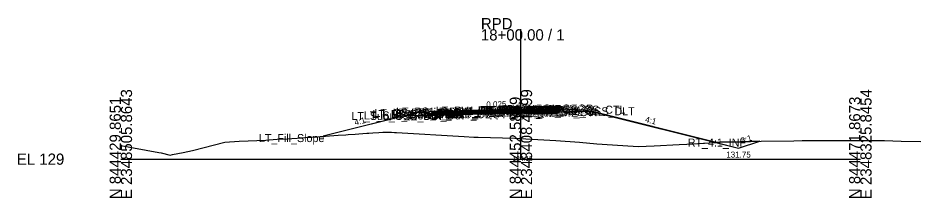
# Model space of a CAD drawing. Extents: x -26 to 2348536, y -510 to 844755.
# Drawn here: x -25.7 to 200, y 2990.3 to 3035.3 of the extents above; entities that cross this region are included whole.
import ezdxf

# ---------------------------------------------------------------- set-up
doc = ezdxf.new("R2010")
doc.units = 0
for name, color, linetype in [('Default', 7, 'Continuous'), ('Exist Cross Section Cell', 7, 'Continuous'), ('Exist XS Center Line Elevation Label', 7, 'Continuous'), ('Exist XS Ground Line', 7, 'Continuous'), ('Prop CMT Pvmt Course 1', 7, 'Continuous'), ('Prop CMT Pvmt Course 2', 7, 'Continuous'), ('Prop CMT Pvmt Course 3', 7, 'Continuous'), ('Prop CMT Pvmt Surface', 7, 'Continuous'), ('Prop CMT Pvmt Surface Shoulder', 7, 'Continuous'), ('Prop CMT Shld Paved Course 1', 7, 'Continuous'), ('Prop CMT Shld Paved Course 2', 7, 'Continuous'), ('Prop CMT Shld Paved Course 3', 7, 'Continuous'), ('Prop CMT Slope Grass', 7, 'Continuous'), ('Prop CMT Subgrade Earthwork', 7, 'Continuous'), ('Prop XS Ditch Standard Text', 7, 'Continuous'), ('Prop XS Earthwork Shape', 7, 'Continuous'), ('Prop XS SE Text', 7, 'Continuous'), ('Prop XS Side Slope Text', 7, 'Continuous'), ('Scratch_Level_0', 7, 'Continuous')]:
    doc.layers.add(name, color=color, linetype=linetype)

msp = doc.modelspace()

# ---------------------------------------------------------------- linework, layer by layer
at = {"layer": 'Exist Cross Section Cell'}
for p, q in [((100, 3000), (100, 3032.45)), ((0, 3000), (100, 3000)), ((100, 3000), (184.85, 3000))]:
    msp.add_line(p, q, dxfattribs=at)
at = {"layer": 'Exist XS Ground Line'}
msp.add_lwpolyline([(0, 3003.38), (9.47, 3001.7), (10.07, 3001.56), (12.37, 3001.02), (12.9, 3001.12), (15.58, 3001.62), (17.88, 3002.12), (25.98, 3004.25), (29.55, 3004.48), (36.25, 3004.75), (37.1, 3004.84), (39.08, 3004.97), (41.57, 3005.09), (42.72, 3005.17), (44.1, 3005.27), (46.87, 3005.46), (47.64, 3005.51), (49.26, 3005.61), (52.19, 3005.83), (54.3, 3005.96), (56.2, 3006.11), (56.84, 3006.15), (58.61, 3006.28), (59.47, 3006.34), (61.45, 3006.47), (62.02, 3006.51), (62.97, 3006.57), (64.5, 3006.68), (65.52, 3006.7), (67.27, 3006.73), (67.68, 3006.71), (68.44, 3006.68), (68.94, 3006.66), (85.83, 3005.64), (88.2, 3005.5), (89.31, 3005.47), (98.47, 3005.23), (100, 3005.15), (101.26, 3005.08), (108.74, 3004.68), (114.65, 3004.21), (119.01, 3003.85), (128.05, 3003.27), (129.28, 3003.2), (133.32, 3003.36), (139.55, 3003.63), (141.44, 3003.75), (149.82, 3004.21), (154.84, 3004.36), (160.09, 3004.53), (168.23, 3004.61), (170.35, 3004.65), (177.33, 3004.65), (180.62, 3004.65), (181.62, 3004.66), (190.89, 3004.68), (195.02, 3004.53), (200, 3004.44)], dxfattribs=at)
at = {"layer": 'Prop CMT Pvmt Course 1'}
for p, q in [((100, 3012.44), (88, 3012.14)), ((88, 3011.89), (100, 3012.19)), ((88, 3012.14), (88, 3011.89)), ((100, 3012.44), (104, 3012.54)), ((100, 3012.19), (100, 3012.44)), ((100, 3012.19), (100, 3012.44)), ((100, 3012.19), (100, 3012.31)), ((100, 3012.31), (100, 3012.31)), ((100, 3012.31), (100, 3012.19)), ((100, 3012.19), (100, 3012.31)), ((100, 3012.31), (100, 3012.31)), ((100, 3012.31), (100, 3012.19)), ((104, 3012.29), (100, 3012.19)), ((100, 3012.19), (100, 3012.19)), ((100, 3012.19), (100, 3012.19)), ((104, 3012.54), (104, 3012.29))]:
    msp.add_line(p, q, dxfattribs=at)
at = {"layer": 'Prop CMT Pvmt Course 2'}
for p, q in [((100, 3012.19), (88, 3011.89)), ((88, 3011.89), (88, 3011.55)), ((88, 3011.55), (100, 3011.85)), ((100, 3012.19), (104, 3012.29)), ((100, 3011.85), (100, 3012.19)), ((100, 3011.85), (100, 3012.19)), ((104, 3011.95), (100, 3011.85)), ((104, 3012.29), (104, 3011.95))]:
    msp.add_line(p, q, dxfattribs=at)
at = {"layer": 'Prop CMT Pvmt Course 3'}
for p, q in [((100, 3011.85), (88, 3011.55)), ((88, 3011.55), (88, 3011.22)), ((88, 3011.22), (100, 3011.52)), ((100, 3011.85), (104, 3011.95)), ((100, 3011.52), (100, 3011.85)), ((100, 3011.52), (100, 3011.85)), ((104, 3011.62), (100, 3011.52)), ((104, 3011.95), (104, 3011.62))]:
    msp.add_line(p, q, dxfattribs=at)
at = {"layer": 'Prop CMT Pvmt Surface'}
for q in [(88, 3012.14), (104, 3012.54)]:
    msp.add_line((100, 3012.44), q, dxfattribs=at)
at = {"layer": 'Prop CMT Pvmt Surface Shoulder'}
for p, q in [((88, 3012.14), (78, 3011.89)), ((104, 3012.54), (108, 3012.64))]:
    msp.add_line(p, q, dxfattribs=at)
at = {"layer": 'Prop CMT Shld Paved Course 1'}
for p, q in [((78, 3011.89), (77.74, 3011.63)), ((77.74, 3011.63), (88, 3011.89)), ((88, 3012.14), (78, 3011.89)), ((88, 3011.89), (88, 3012.14)), ((104, 3012.54), (108, 3012.64)), ((104, 3012.29), (104, 3012.54)), ((108.24, 3012.39), (104, 3012.29)), ((108, 3012.64), (108.24, 3012.39))]:
    msp.add_line(p, q, dxfattribs=at)
at = {"layer": 'Prop CMT Shld Paved Course 2'}
for p, q in [((77.74, 3011.63), (77.4, 3011.29)), ((77.4, 3011.29), (88, 3011.55)), ((88, 3011.89), (77.74, 3011.63)), ((88, 3011.55), (88, 3011.89)), ((104, 3012.29), (108.24, 3012.39)), ((104, 3011.95), (104, 3012.29)), ((108.57, 3012.07), (104, 3011.95)), ((108.24, 3012.39), (108.57, 3012.07))]:
    msp.add_line(p, q, dxfattribs=at)
at = {"layer": 'Prop CMT Shld Paved Course 3'}
for p, q in [((76.9, 3011.28), (76.56, 3010.93)), ((76.56, 3010.93), (88, 3011.22)), ((77.4, 3011.29), (76.9, 3011.28)), ((88, 3011.55), (77.4, 3011.29)), ((88, 3011.22), (88, 3011.55)), ((104, 3011.95), (108.57, 3012.07)), ((104, 3011.62), (104, 3011.95)), ((109.39, 3011.75), (104, 3011.62)), ((108.57, 3012.07), (109.07, 3012.08)), ((109.07, 3012.08), (109.39, 3011.75))]:
    msp.add_line(p, q, dxfattribs=at)
at = {"layer": 'Prop CMT Slope Grass'}
for p, q in [((74, 3011.57), (50.56, 3005.71)), ((78, 3011.89), (74, 3011.57)), ((108, 3012.64), (116, 3012.36)), ((116, 3012.36), (154.42, 3002.75)), ((154.42, 3002.75), (159.73, 3004.52))]:
    msp.add_line(p, q, dxfattribs=at)
at = {"layer": 'Prop CMT Subgrade Earthwork'}
for p, q in [((76.56, 3010.93), (70.9, 3010.79)), ((88, 3011.22), (76.56, 3010.93)), ((100, 3011.52), (88, 3011.22)), ((100, 3011.52), (104, 3011.62)), ((104, 3011.62), (109.39, 3011.75)), ((109.39, 3011.75), (117.59, 3011.96))]:
    msp.add_line(p, q, dxfattribs=at)
at = {"layer": 'Prop XS Earthwork Shape'}
for points in [[(76.56, 3010.93), (70.9, 3010.79), (50.56, 3005.71), (52.19, 3005.83), (54.3, 3005.96), (56.2, 3006.11), (56.84, 3006.15), (58.61, 3006.28), (59.47, 3006.34), (61.45, 3006.47), (62.02, 3006.51), (62.97, 3006.57), (64.5, 3006.68), (65.52, 3006.7), (67.27, 3006.73), (67.68, 3006.71), (68.44, 3006.68), (68.94, 3006.66), (85.83, 3005.64), (88.2, 3005.5), (89.31, 3005.47), (98.47, 3005.23), (100, 3005.15), (101.26, 3005.08), (108.74, 3004.68), (114.65, 3004.21), (119.01, 3003.85), (128.05, 3003.27), (129.28, 3003.2), (133.32, 3003.36), (139.55, 3003.63), (141.44, 3003.75), (148.81, 3004.15), (117.59, 3011.96), (109.39, 3011.75), (104, 3011.62), (100, 3011.52), (88, 3011.22)], [(148.81, 3004.15), (154.42, 3002.75), (159.73, 3004.52), (154.84, 3004.36), (149.82, 3004.21)]]:
    msp.add_lwpolyline(points, close=True, dxfattribs=at)

# ---------------------------------------------------------------- texts
at = {"layer": 'Default'}
msp.add_text('-', height=0.0001, dxfattribs=at).set_placement((0, 3000))
at = {"layer": 'Exist Cross Section Cell'}
for s, p in [('RPD', (90, 3032.45)), ('18+00.00 / 1', (90, 3029.65)), ('EL 129', (-26, 2998.6))]:
    msp.add_text(s, height=2.8, dxfattribs=at).set_placement(p)
for s, p in [('N 844429.8651', (0, 2990)), ('E 2348505.8643', (2.8, 2990)), ('N 844452.5869', (100, 2990)), ('E 2348408.4799', (102.8, 2990)), ('N 844471.8673', (184.85, 2990)), ('E 2348325.8454', (187.65, 2990))]:
    msp.add_text(s, height=2.8, rotation=90, dxfattribs=at).set_placement(p)
at = {"layer": 'Exist XS Center Line Elevation Label'}
msp.add_text('134.15', height=1.2, dxfattribs=at).set_placement((97.89, 2999.55))
at = {"layer": 'Prop XS Ditch Standard Text'}
msp.add_text('131.75', height=1.5, dxfattribs=at).set_placement((151.33, 3000.39))
at = {"layer": 'Prop XS SE Text'}
msp.add_text('0.025', height=1.5, rotation=1.4321, dxfattribs=at).set_placement((91.38, 3012.9))
at = {"layer": 'Prop XS Side Slope Text'}
for s, rotation, p in [('4:1', 14.0362, (58.58, 3008.4)), ('4:1', 345.9638, (130.94, 3009.28)), ('3:1', 17.8017, (155.23, 3003.85))]:
    msp.add_text(s, height=1.5, rotation=rotation, dxfattribs=at).set_placement(p)
at = {"layer": 'Scratch_Level_0'}
for s, p in [('LT_PV1_OEOT', (78.74, 3011.14)), ('RT_PV2_OEEOP', (89.26, 3011.19)), ('LT_PV2_OEEOP', (89.31, 3011.19)), ('RT_PV1_OEEOP', (89.83, 3011.31)), ('LT_PV1_OEEOP', (89.87, 3011.31)), ('RT_PV2_IEEOP', (89.91, 3011.19)), ('LT_PV2_IEEOP', (89.95, 3011.19)), ('RT_PV1_IEEOP', (90.47, 3011.31)), ('LT_PV1_IEEOP', (90.52, 3011.31)), ('PV2_PGL', (93.91, 3011.19)), ('RT_PV2_OEOT', (94.13, 3011.29)), ('PV1_PGL', (94.47, 3011.44)), ('RT_PV1_OEOT', (94.69, 3011.54)), ('RT_PS3_Shelf_Out', (95.01, 3011.08)), ('RT_PS2_OEOP', (98.43, 3011.39)), ('RT_PS1_OEOP', (98.76, 3011.64)), ('RT_PS3_OEOP', (98.76, 3011.07)), ('RT_Sub_OSS_DLT', (104.94, 3010.96)), ('RT_GS_OS_CTL', (105.32, 3011.36)), ('LT_Sub_OSS_DLT', (57.64, 3009.78)), ('LT_Sub_Trench_Out', (60.76, 3009.93)), ('LT_PS3_Shelf_Out', (62.89, 3010.28)), ('LT_GS_OS_CTL', (63.37, 3010.57)), ('LT_PS3_OEOP', (67.64, 3010.29)), ('LT_PS2_OEOP', (67.98, 3010.63)), ('LT_PS1_OEOP', (68.8, 3010.89)), ('LT_Sub_OEOT', (78.08, 3010.22)), ('LT_PV2_OEOT', (78.17, 3010.89)), ('LT_PV3_OEOT', (78.17, 3010.55)), ('RT_Sub_OEEOP', (89.17, 3010.52)), ('LT_Sub_OEEOP', (89.21, 3010.52)), ('RT_PV3_OEEOP', (89.26, 3010.85)), ('LT_PV3_OEEOP', (89.31, 3010.85)), ('RT_Sub_Trench_Out', (93.55, 3010.75)), ('RT_Sub_OEOT', (94.03, 3010.62)), ('RT_PV3_OEOT', (94.13, 3010.95)), ('LT_Fill_Slope', (34.52, 3004.26)), ('RT_4:1_INF', (141.7, 3003.15))]:
    msp.add_text(s, height=2, dxfattribs=at).set_placement(p)

doc.saveas('drawing.dxf')
